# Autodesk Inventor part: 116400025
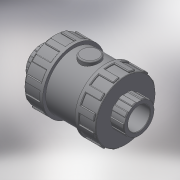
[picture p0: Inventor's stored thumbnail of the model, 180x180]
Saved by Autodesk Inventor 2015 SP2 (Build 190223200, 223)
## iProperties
Created: 2017-11
Part Number: 116400025
Material: Generic
Description: PLASSON FOOT VALVE CEM PVC 25
Document SubType Name: Modeling
Designer: KIM
Density: 1 g/cm^3
Appearance: Default
Author: KIM
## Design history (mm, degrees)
derived "116400 - 116000.ipt"
feature "Solid1::116400 - 116000.ipt"
tag "TaggingFeature1"
body "Solid1"
other parameters: "d0" = 89, "d1" = 25, "d2" = 55, "d3" = 19, "d5" = 13.3, "d7" = 35, "d8" = 49.5, "d13" = 0.75, "d23" = 19, "d24" = 52.8, "d25" = 0.5, "d26" = 0.75, "d27" = 8.25, "d28" = 4.125, "d29" = 14.25, "d30" = 0, "d35" = 0.75, "d39" = 27.5, "d45" = 360 deg, "d47" = 0.5, "d50" = 27.5, "d51" = 16.5, "d53" = 0, "d54" = 1.1, "d56" = 5, "d57" = 2.5, "d59" = 0, "d60" = 0.75, "d62" = 360 deg, "d_" = 25, "l_" = 19, "H_" = 89, "K_" = 55
